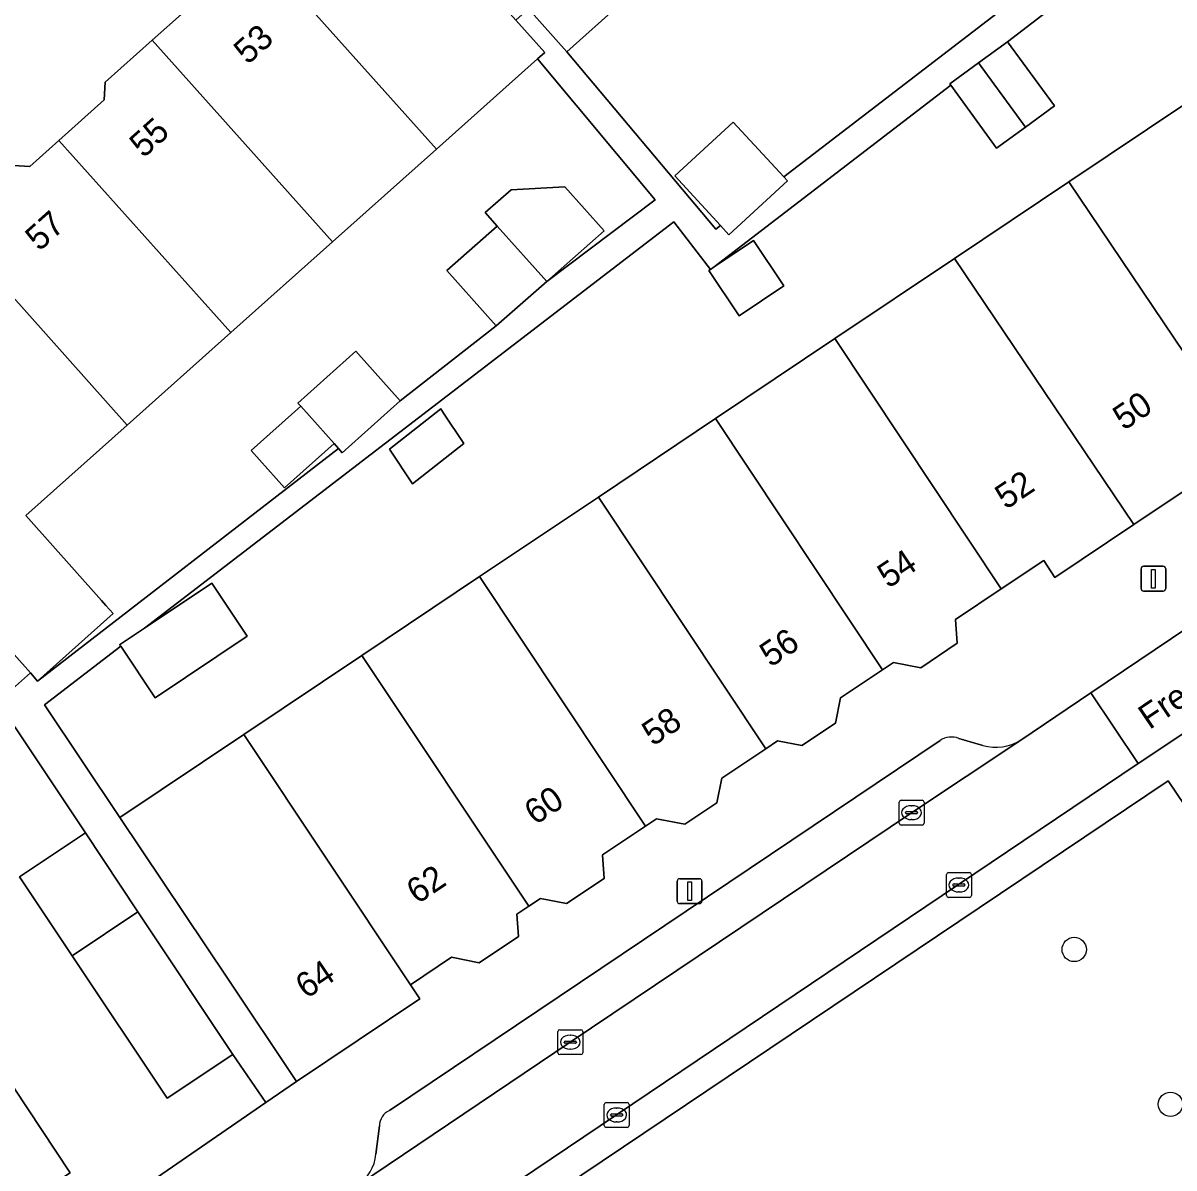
# Model space of a CAD drawing. Extents: x 159960 to 160866, y 382700 to 383354.
# Drawn here: x 160413.42 to 160459.7, y 382881 to 382927.04 of the extents above; entities that cross this region are included whole.
import ezdxf

# ---------------------------------------------------------------- set-up
doc = ezdxf.new("R2010")
doc.units = 0
for name, color, linetype in [('IMGEO_Boom', 7, 'Continuous'), ('IMGEO_Erf', 7, 'Continuous'), ('IMGEO_Groenvoorziening', 7, 'Continuous'), ('IMGEO_Kolk', 7, 'Continuous'), ('IMGEO_Lichtmast', 7, 'Continuous'), ('IMGEO_Openbare_ruimte_label', 7, 'Continuous'), ('IMGEO_Pand', 7, 'Continuous'), ('IMGEO_Pand_nummerreeks', 7, 'Continuous'), ('IMGEO_Parkeervlak_open', 7, 'Continuous'), ('IMGEO_Rijbaan_lokaal_open', 7, 'Continuous'), ('IMGEO_Voetpad_open', 7, 'Continuous')]:
    doc.layers.add(name, color=color, linetype=linetype)

msp = doc.modelspace()

# ---------------------------------------------------------------- linework, layer by layer
at = {"layer": 'IMGEO_Boom'}
for centre in [(160455.691, 382889.785), (160459.562, 382883.56)]:
    msp.add_circle(centre, 0.489, dxfattribs=at)
at = {"layer": 'IMGEO_Erf'}
for points in [[(160470.674, 382939.854), (160453.01, 382926.291), (160454.896, 382923.709), (160453.733, 382922.859), (160452.571, 382922.011), (160450.726, 382924.538), (160441.216, 382917.24), (160442.793, 382918.296), (160444.016, 382916.472), (160442.218, 382915.268), (160440.996, 382917.092), (160441.06, 382917.135), (160439.588, 382919.051), (160418.304, 382902.711), (160421.008, 382904.522), (160422.436, 382902.39), (160418.734, 382899.91), (160417.348, 382901.977), (160414.279, 382899.621), (160417.316, 382895.089), (160422.306, 382898.432), (160427.051, 382901.611), (160431.783, 382904.782), (160436.558, 382907.981), (160441.267, 382911.137), (160446.065, 382914.351), (160450.884, 382917.58), (160455.475, 382920.656), (160460.225, 382923.839)], [(160437.449, 382927.817), (160435.282, 382925.882), (160441.281, 382918.757), (160441.463, 382918.897), (160439.625, 382920.895), (160441.981, 382923.063), (160444.013, 382920.854), (160467.569, 382938.938)], [(160391.496, 382900.313), (160391.954, 382899.589), (160399.473, 382904.598), (160403.476, 382898.589), (160407.397, 382892.703), (160411.318, 382886.819), (160415.322, 382880.808), (160408.003, 382875.932), (160409.407, 382875.338)], [(160410.766, 382875.384), (160412.656, 382876.385), (160423.19, 382883.633), (160421.859, 382885.567), (160419.212, 382883.804), (160415.394, 382889.535), (160413.28, 382892.709), (160415.927, 382894.472), (160413.088, 382898.734), (160412.802, 382898.543), (160412.146, 382899.51)]]:
    msp.add_lwpolyline(points, dxfattribs=at)
for points in [[(160426.105, 382909.929), (160425.928, 382910.127), (160423.933, 382908.348), (160422.592, 382909.851), (160424.587, 382911.63), (160424.471, 382911.761), (160426.807, 382913.845), (160428.592, 382911.843), (160432.446, 382914.863), (160430.457, 382917.092), (160432.491, 382918.879), (160432.01, 382919.418), (160433.052, 382920.334), (160435.214, 382920.458), (160436.796, 382918.685), (160434.479, 382916.649), (160438.834, 382919.939), (160434.113, 382925.603), (160430.046, 382921.974), (160425.87, 382918.247), (160421.775, 382914.592), (160417.607, 382910.873), (160413.528, 382907.233), (160416.577, 382903.82), (160416.754, 382903.621), (160417.048, 382903.292), (160414.009, 382900.58)], [(160431.148, 382910.134), (160429.076, 382908.514), (160428.151, 382909.905), (160430.224, 382911.525), (160430.335, 382911.357)]]:
    msp.add_lwpolyline(points, close=True, dxfattribs=at)
at = {"layer": 'IMGEO_Groenvoorziening'}
msp.add_lwpolyline([(160443.538, 382867.502), (160445.107, 382868.54), (160445.597, 382867.827), (160468.445, 382883.188), (160467.44, 382884.688), (160460.477, 382895.074), (160459.475, 382896.568), (160435.03, 382880.147)], close=True, dxfattribs=at)
at = {"layer": 'IMGEO_Kolk'}
for p, q in [((160448.652, 382894.862), (160448.652, 382895.714)), ((160448.727, 382895.788), (160449.579, 382895.788)), ((160449.14, 382895.568), (160449.165, 382895.568)), ((160449.653, 382895.714), (160449.653, 382894.862)), ((160448.911, 382895.282), (160448.911, 382895.294)), ((160449.349, 382895.245), (160448.951, 382895.245)), ((160448.954, 382895.331), (160449.352, 382895.331)), ((160449.163, 382895.008), (160449.138, 382895.008)), ((160449.395, 382895.294), (160449.395, 382895.282)), ((160449.579, 382894.788), (160448.727, 382894.788)), ((160450.556, 382891.953), (160450.556, 382892.805)), ((160450.631, 382892.879), (160451.483, 382892.879)), ((160451.044, 382892.659), (160451.069, 382892.659)), ((160451.557, 382892.805), (160451.557, 382891.953)), ((160450.815, 382892.373), (160450.815, 382892.385)), ((160451.253, 382892.336), (160450.855, 382892.336)), ((160450.858, 382892.422), (160451.256, 382892.422)), ((160451.067, 382892.099), (160451.042, 382892.099)), ((160451.299, 382892.385), (160451.299, 382892.373)), ((160451.483, 382891.879), (160450.631, 382891.879)), ((160435.003, 382886.555), (160435.855, 382886.555)), ((160434.928, 382885.629), (160434.928, 382886.481)), ((160435.23, 382886.098), (160435.628, 382886.098)), ((160435.416, 382886.335), (160435.441, 382886.335)), ((160435.929, 382886.481), (160435.929, 382885.629)), ((160435.187, 382886.049), (160435.187, 382886.061)), ((160435.625, 382886.012), (160435.227, 382886.012)), ((160435.439, 382885.775), (160435.414, 382885.775)), ((160435.671, 382886.061), (160435.671, 382886.049)), ((160435.855, 382885.555), (160435.003, 382885.555)), ((160436.792, 382882.703), (160436.792, 382883.555)), ((160436.867, 382883.629), (160437.719, 382883.629)), ((160437.28, 382883.409), (160437.305, 382883.409)), ((160437.793, 382883.555), (160437.793, 382882.703)), ((160437.051, 382883.123), (160437.051, 382883.135)), ((160437.489, 382883.086), (160437.091, 382883.086)), ((160437.094, 382883.172), (160437.492, 382883.172)), ((160437.303, 382882.849), (160437.278, 382882.849)), ((160437.535, 382883.135), (160437.535, 382883.123)), ((160437.719, 382882.629), (160436.867, 382882.629))]:
    msp.add_line(p, q, dxfattribs=at)
for points in [[(160448.652, 382894.862), (160448.652, 382895.714)], [(160448.727, 382895.788), (160449.579, 382895.788)], [(160449.653, 382895.714), (160449.653, 382894.862)], [(160449.579, 382894.788), (160448.727, 382894.788)], [(160450.556, 382891.953), (160450.556, 382892.805)], [(160450.631, 382892.879), (160451.483, 382892.879)], [(160451.557, 382892.805), (160451.557, 382891.953)], [(160451.483, 382891.879), (160450.631, 382891.879)], [(160435.003, 382886.555), (160435.855, 382886.555)], [(160434.928, 382885.629), (160434.928, 382886.481)], [(160435.929, 382886.481), (160435.929, 382885.629)], [(160435.855, 382885.555), (160435.003, 382885.555)], [(160436.792, 382882.703), (160436.792, 382883.555)], [(160436.867, 382883.629), (160437.719, 382883.629)], [(160437.793, 382883.555), (160437.793, 382882.703)], [(160437.719, 382882.629), (160436.867, 382882.629)]]:
    msp.add_lwpolyline(points, dxfattribs=at)
for centre, radius, start, end in [((160448.729, 382895.712), 0.0765, 91.552, 178.448), ((160448.729, 382895.712), 0.0765, 91.552, 178.448), ((160449.577, 382895.712), 0.0765, 1.552, 88.448), ((160449.577, 382895.712), 0.0765, 1.552, 88.448), ((160448.951, 382895.291), 0.0403, 85.8775, 175.7526), ((160448.948, 382895.281), 0.0366, 178.938, 274.7102), ((160449.352, 382895.288), 0.043, 264.8664, 352.4533), ((160449.356, 382895.293), 0.0386, 1.7309, 96.639), ((160448.729, 382894.864), 0.0765, 181.552, 268.448), ((160448.729, 382894.864), 0.0765, 181.552, 268.448), ((160449.577, 382894.864), 0.0765, 271.552, 358.448), ((160449.577, 382894.864), 0.0765, 271.552, 358.448), ((160450.633, 382892.803), 0.0765, 91.552, 178.448), ((160450.633, 382892.803), 0.0765, 91.552, 178.448), ((160451.481, 382892.803), 0.0765, 1.552, 88.448), ((160451.481, 382892.803), 0.0765, 1.552, 88.448), ((160450.855, 382892.382), 0.0403, 85.8775, 175.7526), ((160450.852, 382892.372), 0.0366, 178.938, 274.7102), ((160451.256, 382892.379), 0.043, 264.8664, 352.4533), ((160451.26, 382892.384), 0.0386, 1.7309, 96.639), ((160450.633, 382891.955), 0.0765, 181.552, 268.448), ((160450.633, 382891.955), 0.0765, 181.552, 268.448), ((160451.481, 382891.955), 0.0765, 271.552, 358.448), ((160451.481, 382891.955), 0.0765, 271.552, 358.448), ((160435.005, 382886.479), 0.0765, 91.552, 178.448), ((160435.005, 382886.479), 0.0765, 91.552, 178.448), ((160435.853, 382886.479), 0.0765, 1.552, 88.448), ((160435.853, 382886.479), 0.0765, 1.552, 88.448), ((160435.227, 382886.058), 0.0403, 85.8775, 175.7526), ((160435.632, 382886.06), 0.0386, 1.7309, 96.639), ((160435.005, 382885.631), 0.0765, 181.552, 268.448), ((160435.005, 382885.631), 0.0765, 181.552, 268.448), ((160435.224, 382886.048), 0.0366, 178.938, 274.7102), ((160435.628, 382886.055), 0.043, 264.8664, 352.4533), ((160435.853, 382885.631), 0.0765, 271.552, 358.448), ((160435.853, 382885.631), 0.0765, 271.552, 358.448), ((160436.869, 382883.553), 0.0765, 91.552, 178.448), ((160436.869, 382883.553), 0.0765, 91.552, 178.448), ((160437.717, 382883.553), 0.0765, 1.552, 88.448), ((160437.717, 382883.553), 0.0765, 1.552, 88.448), ((160437.091, 382883.132), 0.0403, 85.8775, 175.7526), ((160437.088, 382883.122), 0.0366, 178.938, 274.7102), ((160437.492, 382883.129), 0.043, 264.8664, 352.4533), ((160437.496, 382883.134), 0.0386, 1.7309, 96.639), ((160436.869, 382882.705), 0.0765, 181.552, 268.448), ((160436.869, 382882.705), 0.0765, 181.552, 268.448), ((160437.717, 382882.705), 0.0765, 271.552, 358.448), ((160437.717, 382882.705), 0.0765, 271.552, 358.448)]:
    msp.add_arc(centre, radius, start, end, dxfattribs=at)
for centre, major_axis, ratio, start_param, end_param in [((160449.139, 382895.288), (-0.387, 0.002), 0.722429, 4.712389, 7.853982), ((160449.164, 382895.288), (-0.39, 0.002), 0.717154, 1.570796, 4.712389), ((160451.043, 382892.379), (-0.387, 0.002), 0.722429, 4.712389, 7.853982), ((160451.068, 382892.379), (-0.39, 0.002), 0.717154, 1.570796, 4.712389), ((160435.415, 382886.055), (-0.387, 0.002), 0.722429, 4.712389, 7.853982), ((160435.44, 382886.055), (-0.39, 0.002), 0.717154, 1.570796, 4.712389), ((160437.279, 382883.129), (-0.387, 0.002), 0.722429, 4.712389, 7.853982), ((160437.304, 382883.129), (-0.39, 0.002), 0.717154, 1.570796, 4.712389)]:
    msp.add_ellipse(centre, major_axis=major_axis, ratio=ratio, start_param=start_param, end_param=end_param, dxfattribs=at)
at = {"layer": 'IMGEO_Lichtmast'}
for p, q in [((160458.381, 382904.297), (160458.381, 382905.097)), ((160458.381, 382905.097), (160458.381, 382904.297)), ((160458.481, 382905.197), (160459.271, 382905.197)), ((160459.271, 382905.197), (160458.481, 382905.197)), ((160459.371, 382905.097), (160459.371, 382904.297)), ((160459.371, 382904.297), (160459.371, 382905.097)), ((160459.271, 382904.197), (160458.481, 382904.197)), ((160458.481, 382904.197), (160459.271, 382904.197)), ((160439.829, 382892.63), (160440.619, 382892.63)), ((160440.619, 382892.63), (160439.829, 382892.63)), ((160439.729, 382891.73), (160439.729, 382892.53)), ((160439.729, 382892.53), (160439.729, 382891.73)), ((160440.719, 382892.53), (160440.719, 382891.73)), ((160440.719, 382891.73), (160440.719, 382892.53)), ((160440.619, 382891.63), (160439.829, 382891.63)), ((160439.829, 382891.63), (160440.619, 382891.63))]:
    msp.add_line(p, q, dxfattribs=at)
for points in [[(160458.801, 382905.072), (160458.951, 382905.072), (160458.951, 382904.322), (160458.801, 382904.322), (160458.801, 382905.072)], [(160440.149, 382892.505), (160440.299, 382892.505), (160440.299, 382891.755), (160440.149, 382891.755), (160440.149, 382892.505)]]:
    msp.add_lwpolyline(points, dxfattribs=at)
for centre, start, end in [((160458.481, 382905.097), 90, 180), ((160458.481, 382905.097), 90, 180), ((160459.271, 382905.097), 0, 90), ((160459.271, 382905.097), 360, 90), ((160458.481, 382904.297), 180, 270), ((160458.481, 382904.297), 180, 270), ((160459.271, 382904.297), 270, 0), ((160459.271, 382904.297), 270, 0), ((160439.829, 382892.53), 90, 180), ((160439.829, 382892.53), 90, 180), ((160440.619, 382892.53), 0, 90), ((160440.619, 382892.53), 360, 90), ((160439.829, 382891.73), 180, 270), ((160439.829, 382891.73), 180, 270), ((160440.619, 382891.73), 270, 0), ((160440.619, 382891.73), 270, 0)]:
    msp.add_arc(centre, 0.1, start, end, dxfattribs=at)
at = {"layer": 'IMGEO_Pand'}
for points in [[(160432.596, 382937.835), (160432.423, 382937.68), (160431.673, 382937.928), (160429.964, 382936.402), (160430.133, 382935.591), (160428.677, 382934.292), (160428.208, 382934.818), (160427.904, 382934.546), (160431.233, 382930.815), (160433.938, 382927.784), (160433.741, 382927.608), (160435.282, 382925.882), (160437.449, 382927.817), (160436.45, 382928.936), (160436.608, 382929.078), (160436.088, 382929.661), (160438.207, 382931.551)], [(160430.499, 382930.23), (160427.17, 382933.961), (160424.914, 382931.947), (160424.876, 382931.287), (160423.118, 382929.718), (160430.046, 382921.974), (160434.113, 382925.603), (160434.4, 382925.86), (160433.239, 382927.16)], [(160423.118, 382929.718), (160421.899, 382928.63), (160421.214, 382928.669), (160418.619, 382926.353), (160425.87, 382918.247), (160430.046, 382921.974)], [(160421.775, 382914.592), (160425.87, 382918.247), (160418.619, 382926.353), (160416.73, 382924.667), (160416.69, 382923.951), (160414.86, 382922.319)], [(160453.01, 382926.291), (160451.847, 382925.442), (160453.733, 382922.859), (160454.896, 382923.709)], [(160451.847, 382925.442), (160450.686, 382924.593), (160450.726, 382924.538), (160452.571, 382922.011), (160453.733, 382922.859)], [(160460.225, 382923.839), (160455.475, 382920.656), (160462.233, 382910.627), (160464.031, 382911.832), (160464.973, 382911.645), (160466.349, 382912.567), (160466.554, 382913.602), (160466.946, 382913.865)], [(160439.625, 382920.895), (160441.463, 382918.897), (160441.8, 382918.531), (160444.156, 382920.699), (160444.013, 382920.854), (160441.981, 382923.063)], [(160417.607, 382910.873), (160421.775, 382914.592), (160414.86, 382922.319), (160413.693, 382921.277), (160413.048, 382921.313), (160410.404, 382918.951)], [(160432.01, 382919.418), (160432.491, 382918.879), (160434.479, 382916.649), (160436.796, 382918.685), (160435.214, 382920.458), (160433.052, 382920.334)], [(160462.233, 382910.627), (160455.475, 382920.656), (160450.884, 382917.58), (160458.095, 382906.88), (160461.277, 382909.012), (160460.826, 382909.684)], [(160417.607, 382910.873), (160410.404, 382918.951), (160403.288, 382912.595), (160406.019, 382909.536), (160411.744, 382903.119), (160413.715, 382900.91), (160414.009, 382900.58), (160417.048, 382903.292), (160416.754, 382903.621), (160416.577, 382903.82), (160413.528, 382907.233)], [(160432.491, 382918.879), (160430.457, 382917.092), (160432.446, 382914.863), (160434.479, 382916.649)], [(160441.216, 382917.24), (160441.06, 382917.135), (160440.996, 382917.092), (160442.218, 382915.268), (160444.016, 382916.472), (160442.793, 382918.296)], [(160450.884, 382917.58), (160446.065, 382914.351), (160452.756, 382904.285), (160454.463, 382905.429), (160454.917, 382904.751), (160458.095, 382906.88)], [(160447.982, 382901.037), (160448.423, 382901.332), (160449.517, 382901.116), (160450.984, 382902.099), (160450.92, 382903.055), (160452.756, 382904.285), (160446.065, 382914.351), (160441.267, 382911.137)], [(160424.587, 382911.63), (160425.928, 382910.127), (160426.105, 382909.929), (160426.256, 382909.76), (160428.592, 382911.843), (160426.807, 382913.845), (160424.471, 382911.761)], [(160425.928, 382910.127), (160424.587, 382911.63), (160422.592, 382909.851), (160423.933, 382908.348)], [(160428.151, 382909.905), (160429.076, 382908.514), (160431.148, 382910.134), (160430.335, 382911.357), (160430.224, 382911.525)], [(160447.982, 382901.037), (160441.267, 382911.137), (160436.558, 382907.981), (160443.287, 382897.86), (160443.76, 382898.177), (160444.741, 382897.983), (160446.092, 382898.888), (160446.293, 382899.905)], [(160431.783, 382904.782), (160438.455, 382894.746), (160438.9, 382895.044), (160440.03, 382894.821), (160441.325, 382895.688), (160441.52, 382896.676), (160443.287, 382897.86), (160436.558, 382907.981)], [(160431.783, 382904.782), (160427.051, 382901.611), (160433.758, 382891.522), (160434.233, 382891.84), (160435.281, 382891.633), (160436.787, 382892.642), (160436.724, 382893.586), (160438.455, 382894.746)], [(160418.304, 382902.711), (160417.305, 382902.042), (160417.348, 382901.977), (160418.734, 382899.91), (160422.436, 382902.39), (160421.008, 382904.522)], [(160411.744, 382903.119), (160409.515, 382901.266), (160411.554, 382898.982), (160412.146, 382899.51), (160413.715, 382900.91)], [(160422.306, 382898.432), (160429.002, 382888.367), (160430.648, 382889.47), (160431.762, 382889.25), (160433.342, 382890.309), (160433.282, 382891.203), (160433.758, 382891.522), (160427.051, 382901.611)], [(160422.306, 382898.432), (160417.316, 382895.089), (160421.641, 382888.636), (160424.424, 382884.482), (160429.38, 382887.802), (160429.002, 382888.367)], [(160415.394, 382889.535), (160418.041, 382891.298), (160415.927, 382894.472), (160413.28, 382892.709)], [(160415.394, 382889.535), (160419.212, 382883.804), (160421.859, 382885.567), (160418.041, 382891.298)], [(160411.318, 382886.819), (160403.799, 382881.809), (160407.803, 382875.799), (160408.003, 382875.932), (160415.322, 382880.808)]]:
    msp.add_lwpolyline(points, close=True, dxfattribs=at)
at = {"layer": 'IMGEO_Parkeervlak_open'}
for points in [[(160426.869, 382880.292), (160435.426, 382886.052), (160449.15, 382895.284), (160453.54, 382898.204)], [(160450.295, 382898.194), (160428.151, 382883.308)], [(160452.022, 382897.988), (160451.055, 382898.276)], [(160427.749, 382882.692), (160427.614, 382881.551)]]:
    msp.add_lwpolyline(points, dxfattribs=at)
for centre, radius, start, end in [((160450.761, 382897.438), 0.888, 70.6624, 121.6538), ((160452.533, 382899.841), 1.922, 254.5896, 301.6072), ((160428.451, 382882.673), 0.702, 115.2898, 178.4535), ((160425.87, 382881.733), 1.754, 304.7323, 354.0387)]:
    msp.add_arc(centre, radius, start, end, dxfattribs=at)
at = {"layer": 'IMGEO_Rijbaan_lokaal_open'}
for points in [[(160458.264, 382897.258), (160466.706, 382902.882), (160464.776, 382905.783), (160456.356, 382900.103)], [(160458.264, 382897.258), (160456.356, 382900.103), (160453.54, 382898.204), (160449.15, 382895.284), (160435.426, 382886.052), (160426.869, 382880.292), (160426.218, 382879.854), (160423.183, 382877.815), (160413.594, 382871.373), (160415.535, 382868.488), (160415.611, 382868.38), (160421.52, 382872.518)]]:
    msp.add_lwpolyline(points, close=True, dxfattribs=at)
at = {"layer": 'IMGEO_Voetpad_open'}
for points in [[(160410.07, 382861.949), (160415.268, 382865.398), (160416.783, 382866.403), (160416.621, 382866.647), (160416.118, 382867.403), (160433.527, 382879.124), (160435.03, 382880.147), (160459.475, 382896.568), (160460.477, 382895.074), (160462.489, 382896.421), (160465.846, 382898.668), (160467.857, 382900.011), (160495.193, 382918.403), (160496.721, 382919.422), (160500, 382921.626), (160543.226, 382950.68), (160544.698, 382951.695), (160563.415, 382964.323)], [(160413.088, 382898.734), (160415.927, 382894.472), (160418.041, 382891.298), (160421.859, 382885.567), (160423.19, 382883.633), (160424.424, 382884.482), (160421.641, 382888.636), (160417.316, 382895.089), (160414.279, 382899.621), (160417.348, 382901.977), (160417.305, 382902.042), (160418.304, 382902.711), (160439.588, 382919.051), (160441.06, 382917.135), (160441.216, 382917.24), (160450.726, 382924.538), (160450.686, 382924.593), (160451.847, 382925.442), (160453.01, 382926.291), (160470.674, 382939.854)], [(160467.569, 382938.938), (160444.013, 382920.854), (160444.156, 382920.699), (160441.8, 382918.531), (160441.463, 382918.897), (160441.281, 382918.757), (160435.282, 382925.882), (160433.741, 382927.608), (160433.239, 382927.16), (160434.4, 382925.86), (160434.113, 382925.603), (160438.834, 382919.939), (160434.479, 382916.649), (160432.446, 382914.863), (160428.592, 382911.843), (160426.256, 382909.76), (160426.105, 382909.929), (160414.009, 382900.58), (160413.715, 382900.91), (160412.146, 382899.51)], [(160413.048, 382921.313), (160413.693, 382921.277), (160414.86, 382922.319), (160416.69, 382923.951), (160416.73, 382924.667), (160418.619, 382926.353), (160421.214, 382928.669)], [(160461.277, 382909.012), (160458.095, 382906.88), (160454.917, 382904.751), (160454.463, 382905.429), (160452.756, 382904.285), (160450.92, 382903.055), (160450.984, 382902.099), (160449.517, 382901.116), (160448.423, 382901.332), (160447.982, 382901.037), (160446.293, 382899.905), (160446.092, 382898.888), (160444.741, 382897.983), (160443.76, 382898.177), (160443.287, 382897.86), (160441.52, 382896.676), (160441.325, 382895.688), (160440.03, 382894.821), (160438.9, 382895.044), (160438.455, 382894.746), (160436.724, 382893.586), (160436.787, 382892.642), (160435.281, 382891.633), (160434.233, 382891.84), (160433.758, 382891.522), (160433.282, 382891.203), (160433.342, 382890.309), (160431.762, 382889.25), (160430.648, 382889.47), (160429.002, 382888.367), (160429.38, 382887.802), (160424.424, 382884.482), (160423.19, 382883.633), (160412.656, 382876.385)], [(160453.54, 382898.204), (160456.356, 382900.103), (160464.776, 382905.783), (160465.099, 382906.001)], [(160467.177, 382903.196), (160466.706, 382902.882), (160458.264, 382897.258), (160421.52, 382872.518), (160415.611, 382868.38), (160413.308, 382866.834), (160406.587, 382862.392), (160408.916, 382860.279)], [(160428.151, 382883.308), (160450.295, 382898.194)], [(160451.055, 382898.276), (160452.022, 382897.988)], [(160427.614, 382881.551), (160427.749, 382882.692)]]:
    msp.add_lwpolyline(points, dxfattribs=at)
for centre, radius, start, end in [((160450.761, 382897.438), 0.888, 70.6624, 121.6538), ((160452.533, 382899.841), 1.922, 254.5896, 301.6072), ((160428.451, 382882.673), 0.702, 115.2898, 178.4535), ((160425.87, 382881.733), 1.754, 304.7323, 354.0387)]:
    msp.add_arc(centre, radius, start, end, dxfattribs=at)

# ---------------------------------------------------------------- texts
at = {"layer": 'IMGEO_Openbare_ruimte_label'}
msp.add_text('Frederika van Pruisenweg', height=1, rotation=34.0716, dxfattribs=at).set_placement((160458.715, 382898.604))
at = {"layer": 'IMGEO_Pand_nummerreeks'}
for s, rotation, p in [('53', 41.8364, (160422.455, 382925.338)), ('55', 41.8364, (160418.264, 382921.585)), ('57', 41.8364, (160414.072, 382917.833)), ('50', 33.8397, (160457.684, 382910.631)), ('52', 33.8397, (160452.945, 382907.453)), ('54', 33.8397, (160448.215, 382904.281)), ('56', 33.8397, (160443.481, 382901.108)), ('58', 33.8397, (160438.749, 382897.936)), ('60', 33.8397, (160434.016, 382894.762)), ('62', 33.8397, (160429.277, 382891.585)), ('64', 33.8179, (160424.813, 382887.775))]:
    msp.add_text(s, height=1, rotation=rotation, dxfattribs=at).set_placement(p)

doc.saveas('drawing.dxf')
